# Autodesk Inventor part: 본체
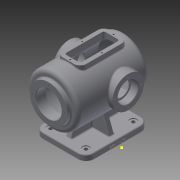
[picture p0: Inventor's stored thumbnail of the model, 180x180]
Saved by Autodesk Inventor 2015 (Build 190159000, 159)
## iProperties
Created: 2021-11
Part Number: 본체
Material: 일반
Document SubType Name: Modeling
Designer: now
Density: 1 g/cm^3
Appearance: 기본값
Author: now
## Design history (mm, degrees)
sketch "스케치1"
  geometry: L1 (-65, 80)-(65, 80); L2 (65, 80)-(65, -80); L3 (65, -80)-(-65, -80); L4 (-65, -80)-(-65, 80); L5 (-65, 80)-(65, -80); L6 (65, 80)-(-65, -80); 1 further point
  constraints: 12 end point, 2 midpoint, 2 parallel, 1 horizontal, 1 perpendicular
  dimensions: "d0" = 130 distance of L2.end L3.end; "d1" = 160 distance of L1.end L2.end
extrude "돌출1" new body sketch "스케치1" distance "d2" = 14; taper "d3" = 0 deg
fillet "모깎기1" dims "d4" = 20
sketch "스케치2"
  geometry: A1 r 20 centre (-45, 60) between (-45, 80) and (-65, 60) reference; A2 r 20 centre (-45, -60) between (-65, -60) and (-45, -80) reference; A3 r 20 centre (45, -60) between (45, -80) and (65, -60) reference; A4 r 20 centre (45, 60) between (65, 60) and (45, 80) reference; 1 further point
hole "구멍1" sketch "스케치2" at (-45, -60), (-45, 60), (45, 60), (45, -60) diameter "d5" = 9; stored, may be unused: countersink angle "d9" = 90 deg, drill point angle "d11" = 118 deg; dims "d6" = 6, "d7" = 18, "d8" = 2, "d10" = 8
fillet "모깎기2" dims "d12" = 3
sketch "스케치3"
  geometry: L1 (-7, -60)-(7, -60); L2 (7, -60)-(7, 60); L3 (7, 60)-(-7, 60); L4 (-7, 60)-(-7, -60); L5 (-7, -60)-(7, 60); L6 (7, -60)-(-7, 60); L7 (-50, 7)-(50, 7); L8 (50, 7)-(50, -7); L9 (50, -7)-(-50, -7); L10 (-50, -7)-(-50, 7); L11 (-50, 7)-(50, -7); L12 (50, 7)-(-50, -7); 1 further point
  constraints: 24 end point, 4 midpoint, 4 parallel, 2 horizontal, 2 perpendicular
  dimensions: "d13" = 120 distance of L1.end L2.end; "d14" = 14 distance of L1.start L1.end; "d15" = 14 distance of L7.end L8.end; "d16" = 100 distance of L8.end L9.end
extrude "돌출2" join sketch "스케치3" distance "d17" = 100; taper "d18" = 0 deg
feature "면 기울기1" dims angle "d19" = 20 deg
feature "면 기울기2" dims angle "d20" = 20 deg
fillet "모깎기3" dims "d21" = 3
fillet "모깎기4" dims "d22" = 3
sketch "스케치4"
  geometry: L1 (62.101, 14)-(77, 14) reference; L2 (80, 11)-(80, 0) reference; L3 (80, 0)-(-80, 0) reference; L4 (-80, 0)-(-80, 11) reference; L5 (-77, 14)-(-62.101, 14) reference; L6 (-59.282, 15.974)-(-23.603, 114) reference; L7 (-23.603, 114)-(23.603, 114) reference; L8 (23.603, 114)-(59.282, 15.974) reference; L9 (100, 114)-(-100, 114); L10 (-100, 114)-(-100, 179); L11 (-100, 179)-(100, 114); L12 (99.021, 184.824)-(-100, 114); L13 (-100, 179)-(75.993, 179); A1 r 3 centre (62.101, 17) between (59.282, 15.974) and (62.101, 14) reference; A2 r 3 centre (77, 11) between (80, 11) and (77, 14) reference; A3 r 3 centre (-77, 11) between (-77, 14) and (-80, 11) reference; A4 r 3 centre (-62.101, 17) between (-62.101, 14) and (-59.282, 15.974) reference; A5 r 100 centre (0, 114) between (100, 114) and (75.993, 179); 2 further points
  constraints: 10 end point, 2 point on circle, 2 point on line, 1 centre point, 1 horizontal
  dimensions: "d23" = 20 distance between parallel lines of L4 L10; "d26" = 114 distance between parallel lines of L9 L3; "d28" = 200 distance from line of L9.start L10; "d37" = 65 distance between parallel lines of L13 L9; "d38" = 175.99342 distance of L10.end L13.end; "d39" = 100 radius of A5
revolve "회전1" sketch "스케치4" stored, may be unused: angle "d32" = 90 deg
sketch "스케치5"
  geometry: C1 r 65 at (0, 0) reference; C2 r 47.5 at (0, 0); 1 further point
  constraints: 1 centre point, 1 coincident
  dimensions: "d33" = 95 diameter of C2
extrude "돌출3" join sketch "스케치5" distance "d34" = 10; taper "d35" = 0 deg
sketch "스케치6"
  geometry: C1 r 47.5 at (0, 0) reference; 1 further point
hole "구멍2" sketch "스케치6" at (0, 0) diameter "d40" = 65; stored, may be unused: countersink angle "d44" = 90 deg, drill point angle "d46" = 0 deg; dims "d41" = 6, "d42" = 4, "d43" = 2, "d45" = 25
chamfer "모따기1" distance "d47" = 1; stored, may be unused: second distance "d48" = 2, angle "d49" = 45 deg
sketch "스케치7"
  geometry: L1 (62.101, 14)-(77, 14) reference; L2 (80, 11)-(80, 0) reference; L3 (80, 0)-(-80, 0) reference; L4 (-80, 0)-(-80, 11) reference; L5 (-77, 14)-(-62.101, 14) reference; L6 (-59.282, 15.974)-(-47.261, 49) reference; L7 (-47.261, 49)-(-100, 49) reference; L8 (-100, 49)-(-100, 66.5) reference; L9 (-100, 66.5)-(-110, 66.5) reference; L10 (-110, 66.5)-(-110, 80.5) reference; L11 (-110, 80.5)-(-109, 81.5) reference; L12 (-109, 81.5)-(-85, 81.5) reference; L13 (-85, 81.5)-(-85, 146.5) reference; L14 (-85, 146.5)-(-109, 146.5) reference; L15 (-109, 146.5)-(-110, 147.5) reference; L16 (-110, 147.5)-(-110, 161.5) reference; L17 (-110, 161.5)-(-100, 161.5) reference; L18 (-100, 161.5)-(-100, 179) reference; L19 (-100, 179)-(75.993, 179) reference; L20 (75.993, 49)-(47.261, 49) reference; L21 (47.261, 49)-(59.282, 15.974) reference; L22 (-85, 169)-(71.239, 169); L23 (-85, 146.5)-(-85, 81.5) reference; L24 (-85, 114)-(90, 114); L25 (-85, 169)-(-85, 114); A1 r 3 centre (62.101, 17) between (59.282, 15.974) and (62.101, 14) reference; A2 r 3 centre (77, 11) between (80, 11) and (77, 14) reference; A3 r 3 centre (-77, 11) between (-77, 14) and (-80, 11) reference; A4 r 3 centre (-62.101, 17) between (-62.101, 14) and (-59.282, 15.974) reference; A5 r 100 centre (0, 114) between (75.993, 49) and (75.993, 179) reference; A6 r 90 centre (0, 114) between (90, 114) and (71.239, 169); 2 further points
  constraints: 6 end point, 2 midpoint, 2 point on circle, 1 centre point, 1 perpendicular, 1 vertical alignment
  dimensions: "d50" = 156.23903 distance of L22.start L22.end; "d51" = 55 distance of L22.start L24.start; "d52" = 175 distance of L24.start L24.end; "d53" = 90 radius of A6
revolve "회전2" sketch "스케치7" stored, may be unused: angle "d54" = 90 deg
fillet "모깎기5" dims "d55" = 3
fillet "모깎기6" dims "d56" = 10
sketch "스케치8"
  geometry: C1 r 47.5 at (0, 0) reference; 2 further points
  constraints: 1 vertical alignment
  dimensions: "d57" = 40 distance of C1.centre point (0, 40)
hole "구멍3" sketch "스케치8" at (0, 40) diameter "d58" = 3.242; stored, may be unused: countersink angle "d62" = 90 deg, drill point angle "d64" = 118 deg; dims "d59" = 11, "d60" = 4, "d61" = 2, "d63" = 13
node "작업 평면1"
sketch "스케치9"
  geometry: L1 (30, -60)-(-30, -60); L2 (-30, -60)-(-30, 60); L3 (-30, 60)-(30, 60); L4 (30, 60)-(30, -60); L5 (30, -60)-(-30, 60); L6 (-30, -60)-(30, 60); L7 (-47.5, -110)-(47.5, -110) reference; 4 further points
  constraints: 12 end point, 4 midpoint, 2 parallel, 1 horizontal, 1 perpendicular, 1 vertical alignment
  dimensions: "d69" = 120 distance of L3.end L1.start; "d70" = 50 distance between parallel lines of L1 L7; "d71" = 60 distance of L1.start L1.end
extrude "돌출4" join sketch "스케치9" stored distance "d72" = 10; taper "d73" = 0 deg
sketch "스케치10"
  geometry: L1 (-20, -50)-(20, -50); L2 (20, -50)-(20, 50); L3 (20, 50)-(-20, 50); L4 (-20, 50)-(-20, -50); 1 further point
  constraints: 8 end point
extrude "돌출5" cut sketch "스케치10" distance "d74" = 47.5; taper "d75" = 0 deg
fillet "모깎기7" dims "d76" = 15
fillet "모깎기8" dims "d77" = 5
fillet "모깎기9" dims "d78" = 3
fillet "모깎기10" dims "d79" = 3
sketch "스케치11"
  geometry: 2 further points
  constraints: 1 horizontal alignment
  dimensions: "d80" = 25 distance of point (-25, 0) point (0, 0)
hole "구멍4" sketch "스케치11" at (-25, 0) diameter "d81" = 3.242; stored, may be unused: countersink angle "d85" = 90 deg, drill point angle "d87" = 118 deg; dims "d82" = 9, "d83" = 4, "d84" = 2, "d86" = 11
sketch "스케치12"
  geometry: 2 further points
  constraints: 1 vertical alignment
  dimensions: "d88" = 55 distance of point (0, 0) point (0, -55)
hole "구멍5" sketch "스케치12" at (0, -55) diameter "d89" = 3.242; stored, may be unused: countersink angle "d93" = 90 deg, drill point angle "d95" = 118 deg; dims "d90" = 9, "d91" = 4, "d92" = 2, "d94" = 11
node "작업 평면2"
node "작업 평면3"
sketch "스케치13"
  geometry: 1 further point
sketch "스케치14"
  geometry: L1 (60, 0)-(-60, 0) reference; C1 r 40 at (17, 114); 1 further point
  constraints: 1 centre point
  dimensions: "d98" = 17 horizontal distance of point (0, 0) C1.centre; "d99" = 80 diameter of C1; "d100" = 114 distance from line of C1.centre L1
extrude "돌출6" join sketch "스케치14" stored distance "d101" = 47.5; taper "d102" = 0 deg
fillet "모깎기11" dims "d103" = 3
sketch "스케치15"
  geometry: C1 r 40 at (0, 0) reference; 1 further point
hole "구멍6" sketch "스케치15" at (0, 0) diameter "d104" = 42; stored, may be unused: countersink angle "d108" = 90 deg, drill point angle "d110" = 0 deg; dims "d105" = 9, "d106" = 52, "d107" = 18, "d109" = 11
sketch "스케치16"
  geometry: C1 r 40 at (0, 0) reference; 1 further point
hole "구멍7" sketch "스케치16" at (0, 0) diameter "d111" = 42; stored, may be unused: countersink angle "d115" = 90 deg, drill point angle "d117" = 0 deg; dims "d112" = 9, "d113" = 52, "d114" = 18, "d116" = 11
fillet "모깎기12" dims "d118" = 0.3
sketch "스케치17"
  geometry: C1 r 26 at (0, 0) reference; 2 further points
  constraints: 1 horizontal alignment
  dimensions: "d119" = 32.5 distance of C1.centre point (-32.5, 0)
hole "구멍8" sketch "스케치17" at (-32.5, 0) diameter "d120" = 3.242; stored, may be unused: countersink angle "d124" = 90 deg, drill point angle "d126" = 0 deg; dims "d121" = 11, "d122" = 52, "d123" = 18, "d125" = 13
chamfer "모따기2" distance "d130" = 1; stored, may be unused: second distance "d131" = 2, angle "d132" = 45 deg
sketch "스케치18"
  geometry: L1 (0, 120)-(0, 0) reference; 3 further points
  constraints: 1 horizontal alignment, 1 midpoint, 1 other
  dimensions: "d133" = 5 distance from line of point (-5, 60) L1
feature "엠보싱1" sketch "스케치18" dims "d134" = 0.5, "d135" = 0
fillet "모깎기13" dims "d136" = 3
fillet "모깎기14" dims "d137" = 3
node "솔리드1"
pattern_circular "원형 패턴1" dims angle "d66" = 360 deg
mirror "대칭1"
mirror "대칭2"
mirror "대칭3"
pattern_circular "원형 패턴2" dims angle "d128" = 360 deg
mirror "대칭4"
node "절단 모서리 투영1"
node "절단 모서리 투영2"
other parameters: "d68" = -184, "d96" = 75, "d97" = 17
